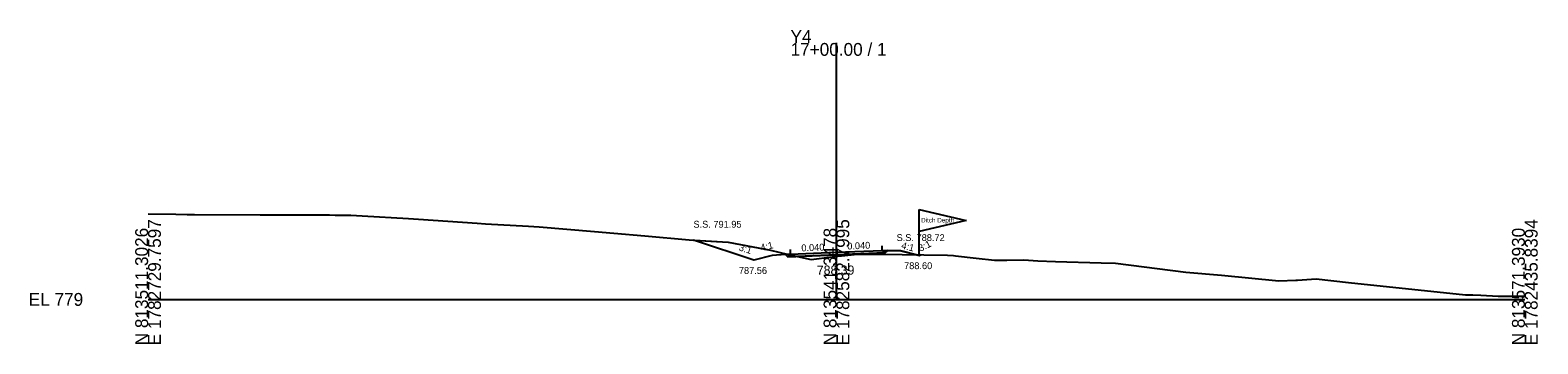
# Model space of a CAD drawing. Extents: x -26 to 3903, y -10 to 9562.
# Drawn here: x -25.7 to 302.8, y 8990.3 to 9058.7 of the extents above; entities that cross this region are included whole.
import ezdxf

# ---------------------------------------------------------------- set-up
doc = ezdxf.new("R2010")
doc.units = 0
for name, color, linetype in [('Exist Cross Section Cell', 7, 'Continuous'), ('Exist XS Center Line Elevation Label', 7, 'Continuous'), ('Exist XS Ground Line', 7, 'Continuous'), ('Prop XS Ditch Slope Text', 7, 'Continuous'), ('Prop XS Ditch Standard Text', 7, 'Continuous'), ('Prop XS Dump Level', 7, 'Continuous'), ('Prop XS Earthwork Shape', 7, 'Continuous'), ('Prop XS EOT Tick Mark', 7, 'Continuous'), ('Prop XS Finish Grade', 7, 'Continuous'), ('Prop XS Finish Grade Earthwork', 7, 'Continuous'), ('Prop XS Finish Grade Pavement', 7, 'Continuous'), ('Prop XS Pvmt Edge Slope', 7, 'Continuous'), ('Prop XS SE Text', 7, 'Continuous'), ('Prop XS Side Slope Text', 7, 'Continuous'), ('Prop XS SS Elevation Text', 7, 'Continuous'), ('Prop XS Subgrade Earthwork', 7, 'Continuous')]:
    doc.layers.add(name, color=color, linetype=linetype)

msp = doc.modelspace()

# ---------------------------------------------------------------- linework, layer by layer
at = {"layer": 'Exist Cross Section Cell'}
for p, q in [((150, 9000), (150, 9055.91)), ((0, 9000), (150, 9000)), ((150, 9000), (300, 9000))]:
    msp.add_line(p, q, dxfattribs=at)
at = {"layer": 'Exist XS Ground Line'}
for p, q in [((0, 9018.64), (6.02, 9018.57)), ((6.02, 9018.57), (8.49, 9018.54)), ((8.49, 9018.54), (10.15, 9018.53)), ((10.15, 9018.53), (24.42, 9018.43)), ((24.42, 9018.43), (39.54, 9018.42)), ((39.54, 9018.42), (40.74, 9018.4)), ((40.74, 9018.4), (41.92, 9018.4)), ((41.92, 9018.4), (44.16, 9018.35)), ((44.16, 9018.35), (46.69, 9018.24)), ((46.69, 9018.24), (56.78, 9017.62)), ((56.78, 9017.62), (58.9, 9017.48)), ((58.9, 9017.48), (71.74, 9016.59)), ((71.74, 9016.59), (73.54, 9016.48)), ((73.54, 9016.48), (82.88, 9015.97)), ((82.88, 9015.97), (85.22, 9015.79)), ((85.22, 9015.79), (97.3, 9014.82)), ((97.3, 9014.82), (101.49, 9014.46)), ((101.49, 9014.46), (108.25, 9013.87)), ((108.25, 9013.87), (117.9, 9013.01)), ((117.9, 9013.01), (126.41, 9012.46)), ((126.41, 9012.46), (135.62, 9010.71)), ((135.62, 9010.71), (139.26, 9009.86)), ((139.26, 9009.86), (144.49, 9008.68)), ((144.49, 9008.68), (149.04, 9009.25)), ((149.04, 9009.25), (150, 9009.39)), ((150, 9009.39), (150.56, 9009.47)), ((150.56, 9009.47), (151.12, 9009.51)), ((151.12, 9009.51), (154.59, 9009.87)), ((154.59, 9009.87), (160.64, 9009.83)), ((160.64, 9009.83), (164.32, 9009.78)), ((164.32, 9009.78), (169.07, 9009.71)), ((169.07, 9009.71), (174.2, 9009.62)), ((174.2, 9009.62), (175.52, 9009.54)), ((175.52, 9009.54), (175.98, 9009.53)), ((175.98, 9009.53), (180.42, 9008.97)), ((180.42, 9008.97), (184.42, 9008.56)), ((184.42, 9008.56), (187.16, 9008.58)), ((187.16, 9008.58), (190.86, 9008.64)), ((190.86, 9008.64), (193.92, 9008.44)), ((193.92, 9008.44), (197.77, 9008.27)), ((197.77, 9008.27), (207.66, 9008)), ((207.66, 9008), (210.81, 9007.9)), ((210.81, 9007.9), (226.13, 9005.97)), ((226.13, 9005.97), (233.91, 9005.29)), ((233.91, 9005.29), (246.43, 9004.02)), ((246.43, 9004.02), (250.14, 9004.22)), ((250.14, 9004.22), (250.47, 9004.21)), ((250.47, 9004.21), (251.51, 9004.28)), ((251.51, 9004.28), (254.56, 9004.47)), ((254.56, 9004.47), (261.56, 9003.66)), ((261.56, 9003.66), (287.05, 9000.99)), ((287.05, 9000.99), (288.68, 9001)), ((288.68, 9001), (290.44, 9000.92)), ((290.44, 9000.92), (294.2, 9000.72)), ((294.2, 9000.72), (299.85, 9000.73)), ((299.85, 9000.73), (300, 9000.72))]:
    msp.add_line(p, q, dxfattribs=at)
at = {"layer": 'Prop XS Dump Level'}
for p, q in [((168, 9014.8), (168, 9019.6)), ((168, 9019.6), (178.3, 9017.2)), ((178.3, 9017.2), (168, 9014.8)), ((168, 9009.6), (168, 9014.8)), ((140, 9009.88), (150, 9010.28)), ((150, 9010.28), (160, 9010.68))]:
    msp.add_line(p, q, dxfattribs=at)
at = {"layer": 'Prop XS Earthwork Shape'}
for points in [[(138.87, 9009.79), (136, 9009.56), (132, 9008.56), (118.83, 9012.95), (126.41, 9012.46), (135.62, 9010.71), (139.26, 9009.86), (141.5, 9009.35), (139.39, 9009.27)], [(141.5, 9009.35), (144.49, 9008.68), (149.04, 9009.25), (150, 9009.39), (150.56, 9009.47), (151.12, 9009.51), (154.59, 9009.87), (160.64, 9009.83), (164.32, 9009.78), (167.44, 9009.74), (164, 9010.6), (161.1, 9010.65), (160.56, 9010.12), (150.02, 9009.69)], [(167.44, 9009.74), (168.37, 9009.72), (168, 9009.6)]]:
    msp.add_lwpolyline(points, close=True, dxfattribs=at)
at = {"layer": 'Prop XS EOT Tick Mark'}
for p, q in [((160, 9010.68), (160, 9011.68)), ((140, 9009.88), (140, 9010.88))]:
    msp.add_line(p, q, dxfattribs=at)
at = {"layer": 'Prop XS Finish Grade'}
for p, q in [((140, 9009.88), (138.87, 9009.79)), ((160, 9010.68), (161.1, 9010.65))]:
    msp.add_line(p, q, dxfattribs=at)
at = {"layer": 'Prop XS Finish Grade Earthwork'}
for p, q in [((132, 9008.56), (118.83, 9012.95)), ((136, 9009.56), (132, 9008.56)), ((138.87, 9009.79), (136, 9009.56)), ((161.1, 9010.65), (164, 9010.6)), ((164, 9010.6), (168, 9009.6)), ((168, 9009.6), (168.37, 9009.72))]:
    msp.add_line(p, q, dxfattribs=at)
at = {"layer": 'Prop XS Finish Grade Pavement'}
for p, q in [((140, 9009.88), (150, 9010.28)), ((150, 9010.28), (160, 9010.68))]:
    msp.add_line(p, q, dxfattribs=at)
at = {"layer": 'Prop XS Pvmt Edge Slope'}
for p, q in [((140, 9009.88), (139.39, 9009.27)), ((160, 9010.68), (160.56, 9010.12))]:
    msp.add_line(p, q, dxfattribs=at)
at = {"layer": 'Prop XS Subgrade Earthwork'}
for p, q in [((139.39, 9009.27), (138.87, 9009.79)), ((139.39, 9009.27), (150.02, 9009.69)), ((150.02, 9009.69), (160.56, 9010.12)), ((160.56, 9010.12), (161.1, 9010.65))]:
    msp.add_line(p, q, dxfattribs=at)

# ---------------------------------------------------------------- texts
at = {"layer": 'Exist Cross Section Cell'}
for s, p in [('Y4', (140, 9055.91)), ('17+00.00 / 1', (140, 9053.11)), ('EL 779', (-26, 8998.6))]:
    msp.add_text(s, height=2.8, dxfattribs=at).set_placement(p)
for s, p in [('N 813511.3026', (0, 8990)), ('E 1782729.7597', (2.8, 8990)), ('N 813541.3478', (150, 8990)), ('E 1782582.7995', (152.8, 8990)), ('N 813571.3930', (300, 8990)), ('E 1782435.8394', (302.8, 8990))]:
    msp.add_text(s, height=2.8, rotation=90, dxfattribs=at).set_placement(p)
at = {"layer": 'Exist XS Center Line Elevation Label'}
msp.add_text('788.39', height=2, dxfattribs=at).set_placement((145.73, 9005.39))
at = {"layer": 'Prop XS Ditch Slope Text'}
for rotation, p in [(14.0362, (133.64, 9010.51)), (345.9638, (164.04, 9011.11))]:
    msp.add_text('4:1', height=1.5, rotation=rotation, dxfattribs=at).set_placement(p)
at = {"layer": 'Prop XS Ditch Standard Text'}
for s, p in [('787.56', (128.74, 9005.56)), ('788.60', (164.74, 9006.6))]:
    msp.add_text(s, height=1.5, dxfattribs=at).set_placement(p)
at = {"layer": 'Prop XS Dump Level'}
for s, height, p in [('Ditch Depth', 1, (168.44, 9016.77)), ('Case1', 0.04, (136, 9009.52)), ('Case1', 0.04, (164, 9010.56))]:
    msp.add_text(s, height=height, dxfattribs=at).set_placement(p)
at = {"layer": 'Prop XS SE Text'}
for p in [(142.38, 9010.47), (152.38, 9010.87)]:
    msp.add_text('0.040', height=1.5, rotation=2.2906, dxfattribs=at).set_placement(p)
at = {"layer": 'Prop XS Side Slope Text'}
for rotation, p in [(342.2871, (128.63, 9010.72)), (26.5651, (168.31, 9010.37))]:
    msp.add_text('3:1', height=1.5, rotation=rotation, dxfattribs=at).set_placement(p)
at = {"layer": 'Prop XS SS Elevation Text'}
for s, p in [('S.S. 791.95', (118.84, 9015.63)), ('S.S. 788.72', (163.11, 9012.72))]:
    msp.add_text(s, height=1.5, dxfattribs=at).set_placement(p)

doc.saveas('drawing.dxf')
